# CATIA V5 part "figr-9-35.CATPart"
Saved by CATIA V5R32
Part number: Part1
Bounding box of the stored display mesh (mm): x -250 to 0, y -60 to 60, z 0 to 100
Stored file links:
  D:\PROJECTS\Project 2022\CATIA V5 6R 2022\Resources\Part Files\c09_catia_v5_6r2022_prt\c09_catia_v5_6r2022_prt\figr-9-35.CATPart
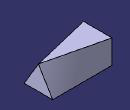
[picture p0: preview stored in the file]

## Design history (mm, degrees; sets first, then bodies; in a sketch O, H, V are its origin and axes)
Body1 (main body)
  Sketch1 on yz-plane, origin (0, 0, 0), H (0, 1, 0), V (0, 0, 1)
    point P1 (-60, 0)
    line L1 (-60, 0) -> (0, 100)
    point P2 (0, 100)
    line L2 (0, 100) -> (60, 0)
    point P3 (60, 0)
    line L3 (60, 0) -> (-60, 0)
    coincidence: P1 H, P2 V, P3 H
    horizontal: L3 H
    midpoint: O L3
  Sketch2, origin (-250, 0, 0), H (0, 1, 0), V (0, 0, 1)
    point P1 (-60, 0)
    line L1 (-60, 0) -> (60, 0)
    line L2 (60, 0) -> (60, 100)
    line L3 (60, 100) -> (-60, 100)
    line L4 (-60, 100) -> (-60, 0)
    coincidence: P1 H
    horizontal: L1 H, L3 H
    vertical: L2 V, L4 V
  Loft1: Sections (Sketch1; Sketch2), SectionCouplingPoints ({coupling CouplingPoints (vertex [element of Sketch1 | element of Sketch1]; vertex [element of Sketch2 | element of Sketch2])}; {coupling CouplingPoints (vertex [element of Sketch1 | element of Sketch1]; vertex [element of Sketch2 | element of Sketch2])}; {coupling CouplingPoints (vertex [element of Sketch1 | element of Sketch1]; vertex [element of Sketch2 | element of Sketch2])})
